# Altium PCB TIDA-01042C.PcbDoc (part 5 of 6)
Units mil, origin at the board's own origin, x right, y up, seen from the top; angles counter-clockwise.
Board outline 8300 x 7100 mil, 8 copper layers (Top Layer, Signal Layer 1, Signal Layer 2, Signal Layer 3, Signal Layer 4, Signal Layer 5, Signal Layer 6, Bottom Layer), stack 59.2 mil thick; 551 components, 303 nets, 1611 pads, 2322 vias.
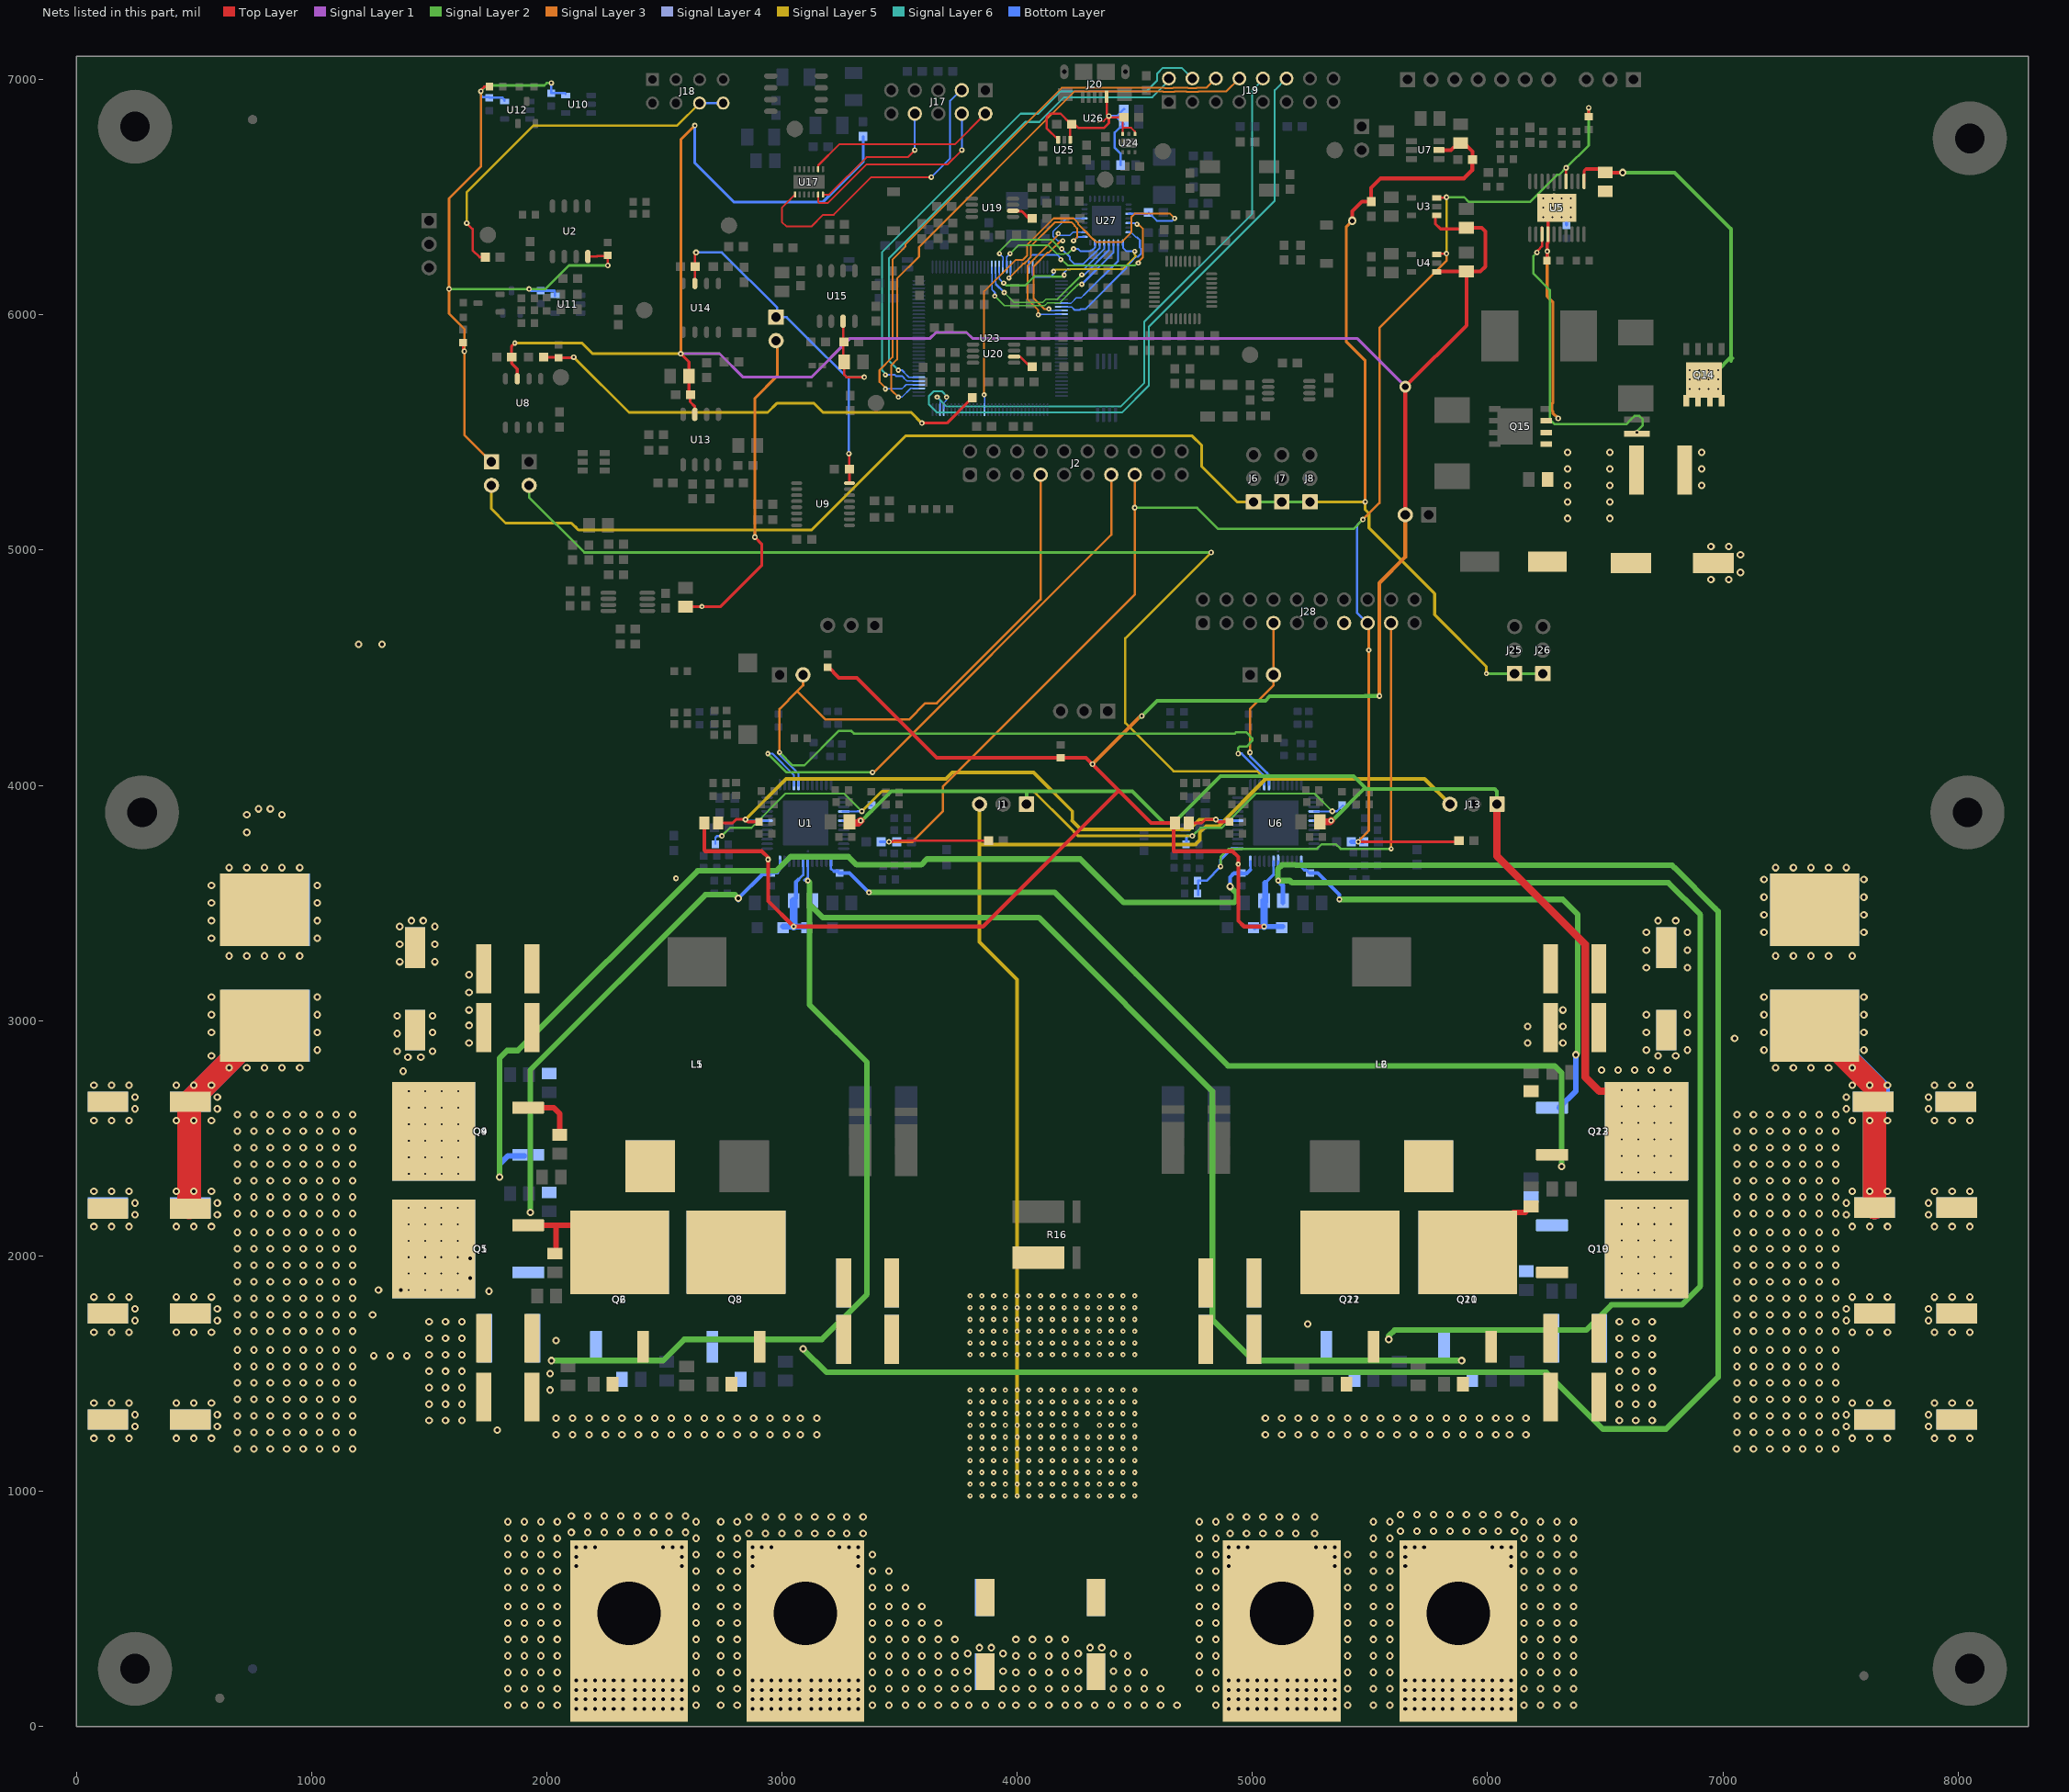
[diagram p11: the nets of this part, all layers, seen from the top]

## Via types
v1: diameter 32, hole 16, Top Layer to Bottom Layer, tented both sides, 1077 vias
v2: diameter 22, hole 8, Top Layer to Bottom Layer, tented both sides, 583 vias
v3: diameter 32, hole 16, Top Layer to Bottom Layer, 233 vias
v4: diameter 24, hole 10, Top Layer to Bottom Layer, tented both sides, 153 vias
v5: diameter 24, hole 8, Top Layer to Bottom Layer, 96 vias
v6: diameter 19.68, hole 7.87, Top Layer to Bottom Layer, 70 vias
v7: diameter 24, hole 10, Top Layer to Bottom Layer, 44 vias
v8: diameter 28, hole 8, Top Layer to Bottom Layer, tented top, 24 vias
v9: diameter 22, hole 8, Top Layer to Bottom Layer, 18 vias
v10: diameter 19.68, hole 8, Top Layer to Bottom Layer, 16 vias
v11: diameter 50, hole 28, Top Layer to Bottom Layer, 3 vias
v12: diameter 36, hole 20, Top Layer to Bottom Layer, 2 vias
v13: diameter 26, hole 12, Top Layer to Bottom Layer, 1 vias
v14: diameter 28, hole 12, Top Layer to Bottom Layer, tented both sides, 1 vias
v15: diameter 24, hole 10, Top Layer to Bottom Layer, tented top, 1 vias

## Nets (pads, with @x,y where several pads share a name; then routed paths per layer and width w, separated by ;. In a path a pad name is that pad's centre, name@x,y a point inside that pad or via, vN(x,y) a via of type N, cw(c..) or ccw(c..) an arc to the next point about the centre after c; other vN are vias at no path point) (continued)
OVPB2: C203.1 J28.17 R170.2 U6.25 | length 2057.8
  Signal Layer 2 w10: v4(4865,3655) 4865,3695 4900,3730 5275,3730 5294.87,3749.87 5355.13,3749.87 5375,3730 v2(5590,3730)
  Signal Layer 3 w10: v2(5590,3730) J28.17@5590,4690
  Bottom Layer w10: C203.1@4770,3535 4770,3595 4805,3595 v4(4865,3655)
  Bottom Layer w11: 4911.73,3731.73 U6.25@4937.6,3731.73
  Bottom Layer w12: v4(4865,3655) 4865,3685 4911.73,3731.73
PGND: C10.2 C18.2 C20.2 C21.2 C22.2 C23.2 C24.2 C25.2 C26.2 C27.2 C28.2 C29.2 C32.2 C38.2 C39.2 C40.2 C42.2 C43.2 C47.2 C48.2 C50.2 C51.2 C52.2 C53.2 C54.2 C55.2 C56.2 C57.2 C58.2 C59.2 C60.2 C61.2 C62.2 C63.2 C64.2 C65.2 C66.2 C67.2 C68.2 C69.2 C70.2 C71.2 C193.2 C206.2 C207.2 C208.2 C209.2 C210.2 C211.2 C212.2 C213.2 C214.2 C215.2 C216.2 C217.2 J11.1 J12.1 NT1.2 NT2.2 NT3.2 Q2.3 Q3.3 Q6.3 Q8.3 Q11.3 Q12.3 Q15.1 Q15.2 Q15.3 Q20.3 Q21.3 R24.2 R25.2 R35.2 R36.2 R47.1 R175.2 R176.2 R188.2 R189.2 T3.1 T4.1 U1.18 U5.13 U5.14 U5.21 U6.18 | length 23138
  Top Layer w10: v4@6215,6265 6215,6275 6231.02,6291.02 U5.13@6231.02,6342.8 U5.13@6230,6370
  Top Layer w13: C48.2@6257.44,6230 6253.63,6233.82 v4(6253.63,6270) 6253.63,6303.63 6256.61,6306.61 U5.14@6256.61,6342.8 6256.61,6416.61 U5.21@6295,6455
  Signal Layer 2 w10: v4(6210,6265) 6195,6250 6195,6175.28 6265,6105.28 6265,5555.28 6285.28,5535 6590,5535 6610.13,5555.13 6610.13,5555.3 6624.7,5569.87 6645.3,5569.87 6659.87,5555.3 6659.87,5555.13 6660,5555 6660,5540 6659.87,5539.87 6659.87,5529.87 6635,5505 v7(6635,5500)
  Signal Layer 2 w24: v1(2020,1555) 2495,1555 2585,1645 3170,1645 3361.87,1836.87 3361.87,2823.13 3116.87,3068.13 3116.87,3495 ; v1(3090,1605) 3190,1505 6249.13,1505 ; v4(3110,3595) 3116.87,3588.13 3116.87,3495 ; v1(5580,1645) 5580,1660 5605,1685 6419.92,1685 6526.8,1791.87 6825,1791.87 6904.96,1871.84 6904.96,3449.96 6768.67,3586.25 5168.59,3586.25 5159.85,3595 v4(5110,3595) 5108.13,3596.87 5108.13,3643.2 5126.8,3661.87 5183.13,3661.87 5185,3660 6785,3660 6795,3650 6795.08,3650 6968.71,3476.37 ; v1(5890,1555) 5004.92,1555 4830,1729.92 4830,2699.92 4091.8,3438.13 3173.75,3438.13 3116.87,3495 ; 6250,1505 6249.13,1505 ; 6249.13,1505 6490,1264.13 6759.13,1264.13 6980,1485 6980,3465 ; 6968.71,3476.37 6980,3465.08 6980,3465 ; 6968.71,3476.37 6968.71,3476.29 6980,3465
  Signal Layer 3 w13: v4(6253.63,6270) 6253.63,6079 6277.63,6055 6277.63,5624.92 6273.63,5620.92 6273.63,5595.08 6277.63,5591.08 6277.63,5582.37 v7(6300,5560)
  Bottom Layer w9.8: U6.18@5109.84,3677.6 5109.84,3595.16 v4(5110,3595)
  Bottom Layer w10: 3109.84,3609.63 3109.84,3609.84 U1.18@3109.84,3681.54
  Bottom Layer w12: 3095.35,3595.35 3109.84,3609.84 3110,3610
  Bottom Layer w13: C47.2@6335,6382.56 6335,6435.94 v6(6354.06,6455)
  Bottom Layer w20: v4(5110,3595) 5130,3575 C193.2@5130,3500
  other v1: 2740,90 2810,90 3385,90 3455,90 3525,90 3595,90 3665,90 3735,90 3795,90 3865,90 3935,90 3995,90 4065,90 4135,90 4205,90 4260,90 4330,90 4400,90 4470,90 4540,90 4610,90 4680,90 5515,90 5585,90 6155,90 6225,90 6295,90 6365,90 2740,160 2810,160 3385,160 3455,160 3525,160 3595,160 3665,160 3735,160 3790,160 3940,160 3995,160 4065,160 4135,160 4205,160 4260,160 4410,160 4470,160 4540,160 4610,160 5515,160 5585,160 6155,160 6225,160 6295,160 6365,160 2740,230 2810,230 3385,230 3455,230 3525,230 3595,230 3665,230 3735,230 3995,230 4065,230 4135,230 4205,230 4470,230 4540,230 5515,230 5585,230 6155,230 6225,230 6295,230 6365,230 3790,235 3940,235 4260,235 4410,235 2740,300 2810,300 3385,300 3455,300 3525,300 3595,300 3665,300 3735,300 3995,300 4065,300 4135,300 4205,300 4470,300 5515,300 5585,300 6155,300 6225,300 6295,300 6365,300 3790,310 3940,310 4260,310 4410,310 3840,335 3890,335 4310,335 4360,335 2740,370 2810,370 3385,370 3455,370 3525,370 3595,370 3665,370 3735,370 3995,370 4065,370 4135,370 4205,370 5515,370 5585,370 6155,370 6225,370 6295,370 6365,370 2740,440 2810,440 3385,440 3455,440 3525,440 3595,440 3665,440 5515,440 5585,440 6155,440 6225,440 6295,440 6365,440 2740,510 2810,510 3385,510 3455,510 3525,510 3595,510 5515,510 5585,510 6155,510 6225,510 6295,510 6365,510 2740,590 2810,590 3385,590 3455,590 3525,590 5515,590 5585,590 6155,590 6225,590 6295,590 6365,590 2740,660 2810,660 3385,660 3455,660 5515,660 5585,660 6155,660 6225,660 6295,660 6365,660 2740,730 2810,730 3385,730 5515,730 5585,730 6155,730 6225,730 6295,730 6365,730 2740,800 2810,800 5515,800 5585,800 6155,800 6225,800 6295,800 6365,800 2860,820 2930,820 3000,820 3070,820 3140,820 3210,820 3275,820 3345,820 5630,830 5700,830 5770,830 5840,830 5910,830 5980,830 6045,830 6115,830 2740,870 2810,870 5515,870 5585,870 6155,870 6225,870 6295,870 6365,870 2860,890 2930,890 3000,890 3070,890 3140,890 3210,890 3275,890 3345,890 5630,900 5700,900 5770,900 5840,900 5910,900 5980,900 6045,900 6115,900 75,1225 150,1225 225,1225 7900,1225 7975,1225 8050,1225 2040,1240 2110,1240 2180,1240 2250,1240 2320,1240 2390,1240 2460,1240 2530,1240 2600,1240 2670,1240 2740,1240 2810,1240 2880,1240 2950,1240 3020,1240 3078.24,1240 3148.24,1240 5055,1240 5125,1240 5195,1240 5265,1240 5335,1240 5405,1240 5475,1240 5545,1240 5615,1240 5685,1240 5755,1240 5825,1240 5895,1240 5965,1240 6035,1240 6093.24,1240 6163.24,1240 1790,1260 250,1275 7875,1275 2040,1310 2110,1310 2180,1310 2250,1310 2320,1310 2390,1310 2460,1310 2530,1310 2600,1310 2670,1310 2740,1310 2810,1310 2880,1310 2950,1310 3020,1310 3078.24,1310 3148.24,1310 5055,1310 5125,1310 5195,1310 5265,1310 5335,1310 5405,1310 5475,1310 5545,1310 5615,1310 5685,1310 5755,1310 5825,1310 5895,1310 5965,1310 6035,1310 6093.24,1310 6163.24,1310 250,1325 7875,1325 75,1375 150,1375 225,1375 7900,1375 7975,1375 8050,1375 2015,1430 2015,1500 2040,1640 75,1675 150,1675 225,1675 7900,1675 7975,1675 8050,1675 5235,1710 250,1725 7875,1725 250,1775 7875,1775 75,1825 150,1825 225,1825 7900,1825 7975,1825 8050,1825 75,2125 150,2125 225,2125 7900,2125 7975,2125 8050,2125 250,2175 7875,2175 250,2225 7875,2225 75,2275 150,2275 225,2275 7900,2275 7975,2275 8050,2275 75,2575 150,2575 225,2575 7900,2575 7975,2575 8050,2575 250,2625 7875,2625 250,2675 7875,2675 75,2725 150,2725 225,2725 7900,2725 7975,2725 8050,2725 6170,2905 6320,2905 6170,2975 6320,2975 6320,3045 6675,3225 6850,3225 1375,3250 1525,3250 650,3275 725,3275 800,3275 875,3275 950,3275 7225,3275 7300,3275 7375,3275 7450,3275 7550,3275 6675,3300 6850,3300 1375,3325 1525,3325 575,3350 1025,3350 6675,3375 6850,3375 7175,3375 7600,3375 1375,3400 1525,3400 575,3425 1025,3425 1425,3425 1475,3425 6725,3425 6800,3425 7175,3450 7600,3450 575,3500 1025,3500 7175,3525 7600,3525 575,3575 1025,3575 7175,3600 7600,3600 650,3650 725,3650 800,3650 875,3650 950,3650 7225,3650 7300,3650 7375,3650 7450,3650 7525,3650 725,3800 725,3875 875,3875 775,3900 825,3900 1200,4600 1300,4600 6520,5135 6340,5205 6520,5205 6340,5275 6520,5275 6340,5345 6520,5345 6340,5415 6520,5415
  other v3: 2875,75 2915,75 2955,75 2995,75 3035,75 3075,75 3125,75 3165,75 3205,75 3245,75 3285,75 3325,75 5650,75 5690,75 5730,75 5770,75 5810,75 5850,75 5900,75 5940,75 5980,75 6020,75 6060,75 6100,75 2875,115 2915,115 2955,115 2995,115 3035,115 3075,115 3125,115 3165,115 3205,115 3245,115 3285,115 3325,115 5650,115 5690,115 5730,115 5770,115 5810,115 5850,115 5900,115 5940,115 5980,115 6020,115 6060,115 6100,115 2875,155 2915,155 2955,155 2995,155 3035,155 3075,155 3125,155 3165,155 3205,155 3245,155 3285,155 3325,155 5650,155 5690,155 5730,155 5770,155 5810,155 5850,155 5900,155 5940,155 5980,155 6020,155 6060,155 6100,155 2875,195 2915,195 2955,195 2995,195 3035,195 3075,195 3125,195 3165,195 3205,195 3245,195 3285,195 3325,195 5650,195 5690,195 5730,195 5770,195 5810,195 5850,195 5900,195 5940,195 5980,195 6020,195 6060,195 6100,195 2875,681.27 3325,681.27 5650,681.27 6100,681.27 2875,721.27 3325,721.27 5650,721.27 6100,721.27 2875,761.27 2915,761.27 2955,761.27 3245,761.27 3285,761.27 3325,761.27 5650,761.27 5690,761.27 5730,761.27 6020,761.27 6060,761.27 6100,761.27 6340,5135
  other v4: 2550,3605
  other v6: 6235.94,6415.63 6275.32,6415.63 6314.69,6415.63 6354.06,6415.63 6235.94,6455 6275.32,6455 6314.69,6455 6235.94,6494.37 6275.32,6494.37 6314.69,6494.37 6354.06,6494.37
SCLK: J17.8 U17.14 | length 624.3
  Top Layer w8: U17.14@3174.06,6510.87 3200.87,6510.87 3360,6670 3535,6670 v7(3565,6700)
  Bottom Layer w8: v7(3565,6700) J17.8@3565,6855
SDIN: J17.4 U17.13 | length 889.3
  Top Layer w8: U17.13@3154.37,6510.87 3155,6510.24 3155,6480 3160,6475 3195,6475 3360,6640 3705,6640 3760,6695 v7@3760,6700
  Bottom Layer w8: v7(3765,6700) J17.4@3765,6855
SDO: J17.3 U17.8 | length 1296.1
  Top Layer w8: U17.8@3055.94,6510.87 3035,6489.92 3034.92,6489.92 3000,6455 3000,6395 3020,6375 3125,6375 3175,6425 3220,6425 3380,6585 v7(3635,6585)
  Bottom Layer w8: v7(3635,6585) 3715,6665 3715,6910 3760,6955 J17.3@3765,6955
SPI_CS: J19.6 U23.36 | length 2436.1
  Signal Layer 3 w8: v2(3440,5685) 3440,5690 3415,5715 3415,5765 3470,5820 3470,6235 3483.62,6248.62 3510.86,6275.86 3524.47,6289.47 3524.47,6299.47 4189.6,6964.6 4237.15,6964.6 4238.42,6965.87 4625.58,6965.87 4627.85,6963.6 4662.15,6963.6 4664.42,6965.87 4725.58,6965.87 4727.85,6963.6 4762.15,6963.6 4764.42,6965.87 4805.87,6965.87 J19.6@4845,7005
  Bottom Layer w6: v2(3440,5685) 3510,5685 3528.15,5703.15 U23.36@3581.85,5703.15
SPI_DONE: J19.12 U23.29 | length 2730.5
  Signal Layer 6 w8: v2(3700,5650) 3700,5655 3680,5675 3645,5675 3625,5655 3625,5620 3660,5585 4445,5585 4560,5700 4560,5950 5095,6485 5095,6955 J19.12@5145,7005
  Bottom Layer w6: U23.29@3689.09,5600 3689.09,5626.61 3700,5637.52 v2(3700,5650)
SPI_DRDY: J19.10 U23.30 | length 2500.5
  Signal Layer 6 w8: v2(3660,5650) 3700,5610 4440,5610 4540,5710 4540,5970 5000,6430 5000,6955 5045,7000 J19.10@5045,7005
  Bottom Layer w6: v2(3660,5650) 3672.4,5637.6 U23.30@3672.4,5596.85
SPI_MISO: J19.2 U23.38 | length 2123.7
  Signal Layer 4 w8: J19.2@4645,6985 J19.2@4645,7005
  Signal Layer 6 w8: v2(3495,5765) 3455,5805 3455,6240 4035,6820 4095,6820 4200,6925 4575,6925 4645,6995 J19.2@4645,7005
  Bottom Layer w6: 3520,5755 3540.35,5734.65 U23.38@3581.85,5734.65
  Bottom Layer w8: v2(3495,5765) 3510,5765 3520,5755
SPI_MOSI: J19.4 U23.37 | length 2360.2
  Signal Layer 6 w8: v2(3440,5745) 3440,5750 3425,5765 3425,6265 4015,6855 4090,6855 4185,6950 4550,6950 4595,6995 4595,7025 4620,7050 4700,7050 J19.4@4745,7005
  Bottom Layer w6: 3520,5730 3531.1,5718.9 U23.37@3581.85,5718.9
  Bottom Layer w8: v2(3440,5745) 3480,5745 3485,5740 3510,5740 3520,5730
SPI_SCLK: J19.8 U23.35 | length 2464.4
  Signal Layer 3 w8: v2(3495,5650) 3465,5680 3465,5785 3490,5810 3490,6154.25 3582.87,6247.13 3582.87,6287.87 4245,6950 4619,6950 4621.28,6947.72 4668.72,6947.72 4671,6950 4719,6950 4721.28,6947.72 4768.72,6947.72 4771,6950 4890,6950 J19.8@4945,7005
  Bottom Layer w6: v2(3495,5650) 3510,5650 3547.4,5687.4 U23.35@3581.85,5687.4
SW1: C7.1 L1.1 Q1.3 Q2.4 Q3.4 Q4.3 R22.1 R29.1 U1.24 | length 2634.9
  Top Layer w24: Q1.3@1920.33,2130 2115,2130 Q2.4@2125,2140 ; Q4.3@1935,2630 2030,2630 2055,2605 R29.1@2055,2515 ; R22.1@2040,2005 2040,2130
  Signal Layer 2 w24: v1(1930,2185) 1930,2789.92 2675.08,3535 2800,3535 v1(2815,3520)
  Bottom Layer w9.8: 2980,3630 2991.73,3641.73 U1.24@2991.73,3681.54
  Bottom Layer w16: v1@2815,3510 v1(2815,3520) 2917.56,3622.56 C7.1@2950,3622.56 ; C7.1@2950,3625 2955,3630 2980,3630
SW2: C12.2 L2.2 Q10.3 Q11.4 Q12.4 Q13.3 R33.2 R40.2 U1.13 | length 4048.4
  Top Layer w24: Q11.4@6090,2130 6090,2165 6110,2185 6160,2185 R33.2@6185,2210
  Signal Layer 2 w24: v4(3370,3545) 4160,3545 4506.33,3198.67 4506.33,3198.59 4896.8,2808.13 6285,2808.13 6315,2778.13 v1(6315,2380)
  Bottom Layer w9.8: U1.13@3208.27,3681.54 3208.27,3644.32 3222.79,3635
  Bottom Layer w16: 3222.79,3635 3237.56,3635 C12.2@3245,3627.56 3287.44,3627.56 v4(3370,3545)
SW3: C192.1 L5.2 Q5.3 Q6.4 Q8.4 Q9.3 R174.1 R182.1 U6.24 | length 4553.9
  Signal Layer 2 w24: v1(1800,2335) 1800,2840.73 1832.13,2872.87 1877.71,2872.87 2641.72,3636.87 2976.8,3636.87 2996.25,3656.33 2996.25,3656.41 3033.59,3693.75 3033.67,3693.75 3036.8,3696.87 3283.2,3696.87 3318.2,3661.87 3591.8,3661.87 3616.8,3686.87 4268.2,3686.87 4453.2,3501.87 4921.8,3501.87 4932.46,3512.54 4932.46,3542.54 v1(4905,3570)
  Bottom Layer w9.8: 4991.73,3641.73 U6.24@4991.73,3677.6
  Bottom Layer w16: v1(4905,3570) 4905,3610 4920,3625 ; C192.1@4955,3627.56 4922.56,3627.56 4920,3625 ; 4991.73,3641.73 4975,3625 4920,3625
  Bottom Layer w24: v1(1800,2335) 1800,2390 1835,2425 Q9.3@1905,2425
SW4: C195.2 L6.1 Q19.3 Q20.4 Q21.4 Q22.3 R185.2 R193.2 U6.13 | length 2155.5
  Signal Layer 2 w24: v4(5370,3515) 6319.92,3515 6383.13,3451.8 6383.13,2863.13 v1(6375,2855)
  Bottom Layer w9.8: U6.13@5208.27,3677.6 5208.27,3651.73 5220,3640
  Bottom Layer w12: 5220,3640 5230,3640 C195.2@5245,3625
  Bottom Layer w16: C195.2@5245,3627.56 5277.44,3627.56 5370,3535 v4(5370,3515) v4@5370,3510
  Bottom Layer w24: Q22.3@6305,2630 6375,2700 v1(6375,2855)
SYNC: J2.7 J3.2 U1.41 U6.40 | length 4789.2
  Signal Layer 2 w10: v2(2990,4140) 3045,4085 3095,4085 3241.13,4231.13 3294.89,4231.13 3306.01,4220 4052.23,4220 4101.58,4220 4925,4220 4930,4225 4975,4225 5000,4200 5000,4190 4975,4165 4945,4165 4940,4160 v4(4940,4135)
  Signal Layer 3 w10: v2(2990,4140) 2990,4325 3065,4400 ; J3.2@3090,4470 3090,4425 3065,4400 ; J2.7@4100,5320 4100,4790.28 3658.6,4348.87 3610.11,4348.87 3541.24,4280 3185,4280 3065,4400
  Bottom Layer w8: v2@2985,4145 v2(2990,4140) 2990,4130 3070.38,4049.62 3070.38,4047.28 3070.47,4047.19 U1.41@3070.47,3998.46
  Bottom Layer w9.8: v4@4935,4135 v4(4940,4135) 4955,4135 5044.33,4045.67 5044.33,4045.37 5050.79,4038.91 U6.40@5050.79,4002.4
SYNCIN: J2.13 U1.40 | length 2360.6
  Signal Layer 2 w10: v2(2940,4135) 3020,4055 v4(3385,4055)
  Signal Layer 3 w10: v4@3385,4050 v4(3385,4055) ; v4@3390,4055 4400,5065 J2.13@4400,5320
  Bottom Layer w8: v2(2940,4135) 2960,4135 3050.79,4044.21 U1.40@3050.79,3998.46
SYNCIN2: J28.13
SYNCn: J17.2 U17.2 | length 820.1
  Top Layer w8: U17.2@3154.37,6619.13 3154.37,6635.61 3243.76,6725 3735,6725 J17.2@3865,6855
  Bottom Layer w8: J17.2@3865,6855 J17.2@3866.5,6853.5
SYNCOUT2: J27.2 J28.7 U6.41 | length 757.4
  Signal Layer 3 w10: v4@4990,4150 4990,4325 5090,4425 J27.2@5090,4470 J28.7@5090,4690
  Bottom Layer w9.8: v4@4990,4145 v4(4990,4140) 4990,4125 5062,4053 5062,4052.69 5070.47,4044.22 U6.41@5070.47,4002.4
USB_VBUS: C179.1 C182.1 C187.2 C188.1 J20.1 R149.2 U24.4 U24.6 U25.1 U25.3 U26.6 | length 1197.9
  Top Layer w8: U26.6@4344.69,6823.19 4368.19,6823.19 4387.5,6842.5 v7(4390,6845) ; U24.6@4449.41,6768.39 C179.1@4449.41,6834.41 ; 4450,6795 4485,6795 4500.59,6779.41 U24.4@4500.59,6768.39
  Top Layer w10: U25.3@4174.41,6744.29 4125,6793.7 4125,6840 4140,6855 4185,6855 C182.1@4225,6815 ; U25.1@4225.59,6744.29 4225.59,6800.59 C182.1@4235,6810 ; C182.1@4231.5,6810 C182.1@4235,6810 ; J20.1@4381.18,6937.6 J20.1@4381.18,6927.6 4381.18,6853.82 v7(4390,6845) 4395,6840 C179.1@4453.5,6840 ; v7@4387.5,6842.5 4390,6840 4390,6815 4370,6795 4260,6795 4245,6810 C182.1@4235,6810 ; C179.1@4449.41,6834.41 C179.1@4450,6835 ; C179.1@4450,6830 C179.1@4450,6835 ; C179.1@4455,6840 C179.1@4450,6835
  Bottom Layer w10: v7(4390,6845) 4420,6845 ; R149.2@4440,6636.5 4440,6685 4415,6710 4415,6775 C187.2@4450,6810 ; C187.2@4453.5,6810 4420,6843.5 4420,6845 ; C188.1@4455,6875 4425,6845 4420,6845
USBCLK: U23.92 U27.1 | length 640.8
  Signal Layer 5 w8: v2(4155,6185) 4161.87,6191.87 4189.53,6191.87 ; 4189.53,6191.88 4210.47,6191.88 4221.88,6191.88 4225,6195 ; 4210.47,6191.87 4224.53,6191.87 4227.65,6195 4450,6195 4505,6250 4500,6255 v2(4500,6270)
  Bottom Layer w6: U23.92@4066.1,6203.15 4066.1,6168.9 4075,6160
  Bottom Layer w8: 4075.41,6160.41 4075.75,6160.75 4140.75,6160.75 4160.51,6180.51 v2@4160.51,6190 ; U27.1@4450,6305 4450,6285 4465,6270 v2(4500,6270)
USBD0: U23.81 U27.3 | length 790.3
  Signal Layer 2 w6: v2(3905,6080) 3945.75,6039.25 4114.81,6039.25 4115.56,6040 4118.13,6040 4128.13,6050 4180,6050 4245,6115
  Signal Layer 2 w8: v2@3905,6075 v2(3905,6080) ; 4245,6115 4260,6130 v2(4275,6130)
  Bottom Layer w6: U23.81@3892.87,6203.15 3892.87,6107.13 3900,6100
  Bottom Layer w8: 3900,6100 3905,6095 v2(3905,6080) ; v2(4275,6130) 4410,6265 U27.3@4410,6305 ; U27.3@4409.53,6305 U27.3@4409.53,6306.69
USBD1: U23.82 U27.4 | length 716.2
  Signal Layer 2 w6: v2(3945,6095) 3986.87,6053.13 4109.06,6053.13 4121.68,6065.75 4170.75,6065.75
  Signal Layer 2 w8: 4170.75,6065.75 v2(4275,6170)
  Bottom Layer w6: U23.82@3908.62,6203.15 3908.62,6131.38 3910,6130
  Bottom Layer w8: 3910,6130 v2(3945,6095) ; v2@4270,6165 v2(4275,6170) 4285,6170 4390,6275 U27.4@4390,6295 ; U27.4@4389.84,6295 U27.4@4389.84,6306.69
USBD2: U23.83 U27.5 | length 593.3
  Signal Layer 2 w8: v2(3942.88,6134.87) 3952.75,6125 4035,6125 4075,6165 4142.65,6165 4145.53,6162.13 4192.13,6162.13 v2@4200,6170
  Bottom Layer w6: U23.83@3924.37,6203.15 3924.37,6155.63 3925,6155
  Bottom Layer w8: 3925,6152.75 v2(3942.88,6134.87) ; v2(4200,6169) 4200,6180 4215,6195 4285,6195 4370,6280 U27.5@4370,6295
USBD3: U23.84 U27.6 | length 632.6
  Signal Layer 2 w8: v2(3925,6260) 3925,6270 3975,6320 4145,6320 4185,6280 v2(4190,6280) v2@4195,6275
  Bottom Layer w6: v2(3925,6260) 3940.12,6244.88 U23.84@3940.12,6203.15
  Bottom Layer w8: v2(3925,6260) v2@3930,6260 ; v2(4190,6280) 4225,6245 4225,6235 4245,6215 4280,6215 4319.13,6254.13 4321.58,6254.13 4350.47,6283.02 U27.6@4350.47,6306.69
USBD4: U23.85 U27.7 | length 497.8
  Signal Layer 2 w6: 4168.13,6260 4179.07,6260 4180.94,6258.13 4199.06,6258.13 4200.93,6260 4215,6260
  Signal Layer 2 w8: v2(3970,6260) 4005,6295 4133.13,6295 4168.13,6260 ; 4215,6260 4235,6280 v2(4240,6280)
  Bottom Layer w6: U23.85@3955.87,6203.15 3955.87,6245.87 v2(3970,6260)
  Bottom Layer w8: v2@3965,6260 v2(3970,6260) ; v2(4240,6280) 4260,6280 4270,6270 4310,6270 4315,6275 4320,6275 4330,6285 ; 4330.79,6285.79 U27.7@4330.79,6306.69
USBD5: U23.86 U27.9 | length 585.3
  Signal Layer 3 w8: v2(3965.35,6156.75) 4025.85,6217.25 4029.7,6217.25 4034.7,6222.25 4035.64,6222.25 4057.75,6244.36 4057.75,6290.3 4161.58,6394.13 4230.87,6394.13 4244.13,6380.87 4244.13,6378.42 4255,6367.55 4255,6330 v2(4240,6315)
  Bottom Layer w6: v2@3965,6160 3971.61,6166.61 U23.86@3971.61,6203.15
  Bottom Layer w8: v2(4240,6315) 4256.1,6331.1 U27.9@4286.69,6331.1
USBD6: U23.106 U27.10 | length 636.4
  Signal Layer 3 w8: v2(4090,6000) 4090,6020 4045,6065 4045,6209.17 4073.62,6237.79 4073.62,6238.62 4175,6340 v2(4175,6345)
  Bottom Layer w6: v2(4090,6000) 4092.36,6002.36 U23.106@4188.15,6002.36 ; v2(4175,6345) 4181.87,6338.13 4224.16,6338.13 4236.82,6350.79 U27.10@4286.69,6350.79
USBD7: U23.105 U27.13 | length 670.9
  Signal Layer 3 w8: v2(4135,6025) 4115,6025 4070,6070 4070,6205 4130,6265 4135,6265 4185,6315 v2(4194.25,6315)
  Bottom Layer w6: v2(4135,6025) 4141.89,6018.11 U23.105@4188.15,6018.11 ; v2@4195,6315 v2(4194.25,6315) 4172.19,6315 4153.13,6334.07 4153.13,6354.06 4189.07,6390 4190,6390 4209.84,6409.84 U27.13@4286.69,6409.84
USBDIR: U23.104 U27.31 | length 569.8
  Bottom Layer w6: U23.104@4188.15,6033.86 4231.14,6033.86 4240,6025 ; U27.31@4473.31,6350.79 4484.54,6350.79 4505.33,6330 4510,6330
  Bottom Layer w8: 4240,6025 4245,6020 4266.24,6020 4270.11,6023.87 4288.87,6023.87 4465,6200 4465,6205 4492.13,6232.13 4492.13,6234.47 4504.78,6247.13 4514.47,6247.13 4527.84,6260.49 4526.94,6261.38 4526.94,6280.4 4521.87,6285.47 4521.87,6318.13 4511.21,6328.79
USBNXT: U23.103 U27.2 | length 392.9
  Bottom Layer w6: U23.103@4188.15,6049.61 4229.61,6049.61 4252.87,6072.87 4272.87,6072.87 4290,6090
  Bottom Layer w8: 4290,6090 4429.21,6229.21 U27.2@4429.21,6306.69
USBRST: R154.2 U23.18 U27.27 | length 1827.9
  Signal Layer 3 w8: v2(3860,5660) 3860,6100 3993.13,6233.13 4023.13,6233.13 4028.13,6238.13 4029.06,6238.13 4041.87,6250.94 4041.87,6296.87 4155,6410 4240,6410 4260,6390 4260,6385 4306.13,6338.87 4306.13,6338.27 4308.28,6336.12 4308.28,6336 4321,6323.28 4321.72,6323.28 4335,6310 4445,6310 4485,6350 4485,6415 4500,6430 4650,6430 v2(4670,6410)
  Bottom Layer w6: v2(3860,5660) 3861.38,5658.62 U23.18@3861.38,5596.85
  Bottom Layer w8: U27.27@4473.31,6429.53 4554.53,6429.53 R154.2@4559.25,6434.25 ; R154.2@4558.5,6435 R154.2@4559.25,6434.25 ; v2(4670,6410) 4660,6400 4593.5,6400 R154.2@4559.25,6434.25
USBSTP: U23.91 U27.29 | length 756.8
  Signal Layer 2 w8: v2(4185.73,6234.63) 4189.63,6234.63 4190,6235 4215,6210 4500,6210 4510,6220 v2(4515,6220)
  Signal Layer 3 w8: v2(4510,6385) 4515,6385 4535,6365 4535,6245 4515,6225 v2(4515,6220)
  Bottom Layer w6: U23.91@4050.35,6203.15 4050.35,6240.35 4065,6255
  Bottom Layer w8: 4065,6255 4170,6255 4185.73,6239.27 v2(4185.73,6234.63) ; U27.29@4473.31,6390.16 v2@4509.84,6390.16
UVLO: J2.15 J28.15 R4.1 R6.2 R34.1 R45.2 R53.1 R60.2 R87.2 U3.3 U4.3 U5.4 | length 8007.4
  Top Layer w10: v4@3450,3760 v4(3455,3760) 3470,3760 3475,3765 R4.1@3878.5,3765 R4.1@3882.44,3765 ; v4(5450,3760) 5875,3760 R34.1@5880,3765 ; U3.3@5777.24,6497.4 U3.3@5784.13,6497.4 5822.4,6497.4 v4(5825,6500) ; U4.3@5785,6260 v4(5825,6260) ; U5.4@6333.39,6567.2 v4@6333.39,6618.39 ; R53.1@6430,6845 v4(6430,6880)
  Signal Layer 2 w10: v4(4500,5180) 4765,5180 4855,5090 5430,5090 v7(5470,5130) ; v4(5825,6500) 5900,6500 5920,6480 6000,6480 6180.07,6480.07 6295,6595 6304.1,6595 v4(6334.1,6625) 6335,6625 6430,6720 v4(6430,6880)
  Signal Layer 3 w10: v4@3455,3755 3460,3760 3555,3760 3685,3890 3685,3995.56 4500,4810.56 v4(4500,5180) 4500,5295 J2.15@4505,5300 ; v4@5447.5,3760 5495,3807.5 v2(5495,4575) 5495,4660 J28.15@5490,4665 ; v7(5470,5130) 5540,5200 5540,5945 5825,6230 v4(5825,6260)
  Signal Layer 5 w10: v4(5825,6260) v4(5825,6500)
  Bottom Layer w10: R60.2@3417.56,3760 R60.2@3421.5,3760 v4(3455,3760) R6.2@3488.5,3760 R6.2@3490,3760 ; v7(5470,5130) 5445,5105 5445,4735 J28.15@5490,4690
  Bottom Layer w20: R45.2@5421.5,3760 v4(5450,3760) R87.2@5470,3760
V5: C99.2 C111.1 C116.1 C117.1 J14.1 U9.16 U14.7 U15.7 | length 1873.3
  Top Layer w10: U14.7@2630,6133.35 2630,6260 v13(2635,6265) ; C116.1@3255,5890 3260,5885 C117.1@3260,5800 ; U15.7@3260,5970 3260,5888.5 C116.1@3263.5,5885 ; C117.1@3265,5800 3265,5745 3275,5735 v4(3350,5735) ; C99.2@3285,5355 3287.2,5352.8 U9.16@3287.2,5284.57 ; C99.2@3286.5,5355 v4@3286.5,5408.5
  Bottom Layer w10: v13(2635,6265) 2745,6265 2980,6030 J14.1@2980,5990 ; J14.1@2975,5985 J14.1@2980,5990 ; 3280,5735 3285,5730 v4(3285,5410) ; v4(3350,5735) 3275,5735 3110,5900 3020,5990 J14.1@2980,5990
V5.0_Control: C76.1 J6.1 J7.1 J8.1 J14.2 J25.1 J26.1 J37.2 L7.2 R10.1 R164.2 U7.5 | length 8939
  Top Layer w12: L7.2@2590,4760 v2(2660,4760) 2740,4760 2913.65,4933.65 2913.65,5026.35 v7(2885,5055)
  Top Layer w16: v12(5425,6400) 5425,6440 5466.5,6481.5 R164.2@5505,6481.5 5505,6540 5545,6580 5900,6580 5935,6615 R10.1@5935,6655 ; U7.5@5790,6700 U7.5@5793.07,6700 5845,6700 5875,6730 C76.1@5885,6730 ; C76.1@5905,6725 5936.5,6693.5 R10.1@5936.5,6660
  Signal Layer 2 w12: J6.1@5005,5205 J7.1@5125,5205 J8.1@5245,5205 ; v2(5995,4475) J25.1@6115,4475 J26.1@6235,4475
  Signal Layer 3 w12: v7(2885,5055) 2885,5645 2980,5740 J14.2@2980,5895 ; v12(5425,6400) 5400,6375 5400,5885 5480,5805 v4(5480,5205)
  Signal Layer 5 w10: J6.1@5005,5205 J6.1@5015,5205
  Signal Layer 5 w12: J37.2@1765,5275 1765,5175 1825,5115 2105,5115 2120.13,5099.87 2120.3,5099.87 2134.87,5085.3 2134.87,5085 2885,5085 ; v7(2885,5055) 2885,5085 ; J6.1@5005,5205 4935,5205 4785,5355 4785,5445 4745,5485 3525,5485 3125,5085 2885,5085 ; J8.1@5245,5205 v4(5480,5205) 5480,5171.75 5495.87,5155.87 5495.87,5094.13 5775,4815 5775,4725 5995,4505 v2(5995,4475)
V5A: C84.1 C91.2 C93.1 C94.2 J37.1 R90.1 R91.1 U2.8 U10.5 U11.5 U12.5 | length 3298
  Top Layer w10: R90.1@1645,5880 1645,5850 v4(1650,5845) ; v4@1720,6955 1735,6970 R91.1@1757.44,6970 ; U2.8@2175,6247.72 2212.72,6247.72 2215,6250 2260,6250 v4(2260,6210)
  Signal Layer 2 w10: v4(1585,6110) v4(1925,6110) 1995,6110 2095,6210 v4(2260,6210) ; v4(1720,6950) 1745,6975 1990,6975 2000,6985 v4(2020,6985)
  Signal Layer 3 w10: v4(1720,6950) 1720,6630 1585,6495 v4(1585,6110) 1585,6005 1650,5940 v4(1650,5845) 1650,5490 J37.1@1765,5375
  Bottom Layer w10: v4(1720,6950) 1720,6935 1730,6925 C91.2@1755,6925 ; C91.2@1755,6922.56 1812.44,6922.56 1820,6915 U12.5@1820,6910 ; v4(1925,6110) 1932.44,6102.56 C93.1@1975,6102.56 2032.44,6102.56 2035,6100 U11.5@2035,6080 ; v4@2020,6975 C94.2@2020,6942.56 2077.44,6942.56 U10.5@2080,6940
V_HV: C6.1 C18.1 C22.1 C23.1 C24.1 C25.1 C32.1 C33.1 C38.1 C39.1 C40.1 C50.1 C51.1 C52.1 C53.1 C56.1 C57.1 C58.1 C59.1 C60.1 C61.1 C62.1 C63.1 C64.1 C65.1 C66.1 C67.1 C206.1 C207.1 C208.1 C209.1 C210.1 C211.1 C212.1 C213.1 C214.1 C215.1 C216.1 C217.1 J1.1 J9.1 J13.1 Q1.4 Q4.4 Q5.4 Q9.4 Q10.4 Q13.4 Q14.5 Q14.6 Q14.7 Q14.8 Q14.9 Q19.4 Q22.4 T1.1 U1.6 U5.1 U6.6 | length 10068.2
  Top Layer w10: C40.1@6485,6620 C40.1@6500,6605
  Top Layer w13: U5.1@6410.16,6567.2 6410.16,6610.16 6420,6620
  Top Layer w16: 6420,6620 C40.1@6485,6620 ; C40.1@6500,6605 v1(6575,6605)
  Top Layer w30: C33.1@5290,3845 5330,3845 v4(5334.84,3849.84)
  Top Layer w32: C6.1@3285.43,3840 3325,3840 v4(3334.84,3849.84) ; J13.1@6040,3925 J13.1@6040,3920 6040,3700 6415,3325 6415,2760 6475,2700 Q13.4@6570,2700
  Top Layer w100: C56.1@480.2,2205 480.2,2655.2 803.94,2978.94 C18.1@813.94,2978.94 ; C32.1@7390,2978.94 7386.06,2978.94 7542.5,2822.5 7645,2720 C53.1@7645,2655 ; C59.1@7644.8,2205 7644.8,2654.8 C53.1@7645,2655 ; 7645,2610 C53.1@7645,2655
  Signal Layer 2 w16: v4(3334.84,3849.84) 3339.84,3849.84 3380,3890 ; 3382.5,3892.5 3465,3975 4040,3975 ; J1.1@4040,3920 4040,3975 ; v4@5339.84,3849.84 5474.18,3984.18 6030.75,3984.18 6040,3975.09 J13.1@6040,3920 ; 5485,3985 5430,4040 4865,4040 4665,3840 4625,3840 4490,3975 4040,3975 ; v1(6575,6605) 6795,6605 7035,6365 7035,5815 ; v8(6980,5765) 7030,5815 7035,5815 ; 7035,5805 7035,5815 ; 7040,5815 7035,5815
  Bottom Layer w9.8: U1.6@3258.46,3849.84 v4(3334.84,3849.84) ; U6.6@5262.4,3849.84 5330.16,3849.84 v4@5335,3845
  Bottom Layer w10: C208.1@465,2220 C208.1@480.2,2235.2
  Bottom Layer w100: C208.1@480.2,2235.2 480.2,2655 810,2984.8 C211.1@810,2985 ; C217.1@7390,2978.94 7660,2708.94 C213.1@7660,2640 ; C213.1@7640,2665 7644.8,2660.2 C214.1@7644.8,2205
  other v1: 1835,90 1905,90 1975,90 2045,90 2635,90 1835,160 1905,160 1975,160 2045,160 2635,160 1835,230 1905,230 1975,230 2045,230 2635,230 1835,300 1905,300 1975,300 2045,300 2635,300 1835,370 1905,370 1975,370 2045,370 2635,370 1835,440 1905,440 1975,440 2045,440 2635,440 1835,510 1905,510 1975,510 2045,510 2635,510 1835,590 1905,590 1975,590 2045,590 2635,590 1835,660 1905,660 1975,660 2045,660 2635,660 1835,730 1905,730 1975,730 2045,730 2635,730 1835,800 1905,800 1975,800 2045,800 2635,800 2105,825 2175,825 2245,825 2315,825 2385,825 2455,825 2520,825 2590,825 1835,870 1905,870 1975,870 2045,870 2635,870 2105,895 2175,895 2245,895 2315,895 2385,895 2455,895 2520,895 2590,895 685,1180 755,1180 825,1180 895,1180 965,1180 1035,1180 1105,1180 1175,1180 7060,1180 7130,1180 7200,1180 7270,1180 7340,1180 7410,1180 7480,1180 425,1225 500,1225 575,1225 7550,1225 7625,1225 7700,1225 685,1250 755,1250 825,1250 895,1250 965,1250 1035,1250 1105,1250 1175,1250 7060,1250 7130,1250 7200,1250 7270,1250 7340,1250 7410,1250 7480,1250 600,1275 7525,1275 1500,1300 1570,1300 1640,1300 6560,1300 6630,1300 6700,1300 685,1320 755,1320 825,1320 895,1320 965,1320 1035,1320 1105,1320 1175,1320 7060,1320 7130,1320 7200,1320 7270,1320 7340,1320 7410,1320 7480,1320 600,1325 7525,1325 1500,1370 1570,1370 1640,1370 6560,1370 6630,1370 6700,1370 425,1375 500,1375 575,1375 7550,1375 7625,1375 7700,1375 685,1390 755,1390 825,1390 895,1390 965,1390 1035,1390 1105,1390 1175,1390 7060,1390 7130,1390 7200,1390 7270,1390 7340,1390 7410,1390 7480,1390 1500,1440 1570,1440 1640,1440 6560,1440 6630,1440 6700,1440 685,1460 755,1460 825,1460 895,1460 965,1460 1035,1460 1105,1460 1175,1460 7060,1460 7130,1460 7200,1460 7270,1460 7340,1460 7410,1460 7480,1460 1500,1510 1570,1510 1640,1510 6560,1510 6630,1510 6700,1510 685,1530 755,1530 825,1530 895,1530 965,1530 1035,1530 1105,1530 1175,1530 7060,1530 7130,1530 7200,1530 7270,1530 7340,1530 7410,1530 7480,1530 1265,1575 1335,1575 1405,1575 1500,1580 1570,1580 1640,1580 6560,1580 6630,1580 6700,1580 685,1600 755,1600 825,1600 895,1600 965,1600 1035,1600 1105,1600 1175,1600 7060,1600 7130,1600 7200,1600 7270,1600 7340,1600 7410,1600 7480,1600 1500,1650 1570,1650 1640,1650 6560,1650 6630,1650 6700,1650 425,1675 500,1675 575,1675 7550,1675 7625,1675 7700,1675 685,1680 755,1680 825,1680 895,1680 965,1680 1035,1680 1105,1680 1175,1680 7060,1680 7130,1680 7200,1680 7270,1680 7340,1680 7410,1680 7480,1680 1500,1720 1570,1720 1640,1720 6560,1720 6630,1720 6700,1720 600,1725 7525,1725 685,1750 755,1750 825,1750 895,1750 965,1750 1035,1750 1105,1750 1175,1750 1260,1750 7060,1750 7130,1750 7200,1750 7270,1750 7340,1750 7410,1750 7480,1750 600,1775 7525,1775 685,1820 755,1820 825,1820 895,1820 965,1820 1035,1820 1105,1820 1175,1820 7060,1820 7130,1820 7200,1820 7270,1820 7340,1820 7410,1820 7480,1820 425,1825 500,1825 575,1825 7550,1825 7625,1825 7700,1825 1755,1850 1285,1855 1380,1855 685,1890 755,1890 825,1890 895,1890 965,1890 1035,1890 1105,1890 1175,1890 7060,1890 7130,1890 7200,1890 7270,1890 7340,1890 7410,1890 7480,1890 1675,1905 685,1960 755,1960 825,1960 895,1960 965,1960 1035,1960 1105,1960 1175,1960 7060,1960 7130,1960 7200,1960 7270,1960 7340,1960 7410,1960 7480,1960 1675,1990 685,2030 755,2030 825,2030 895,2030 965,2030 1035,2030 1105,2030 1175,2030 7060,2030 7130,2030 7200,2030 7270,2030 7340,2030 7410,2030 7480,2030 685,2100 755,2100 825,2100 895,2100 965,2100 1035,2100 1105,2100 1175,2100 7060,2100 7130,2100 7200,2100 7270,2100 7340,2100 7410,2100 7480,2100 425,2125 500,2125 575,2125 7550,2125 7625,2125 7700,2125 600,2175 7525,2175 685,2180 755,2180 825,2180 895,2180 965,2180 1035,2180 1105,2180 1175,2180 7060,2180 7130,2180 7200,2180 7270,2180 7340,2180 7410,2180 7480,2180 600,2225 7525,2225 685,2250 755,2250 825,2250 895,2250 965,2250 1035,2250 1105,2250 1175,2250 7060,2250 7130,2250 7200,2250 7270,2250 7340,2250 7410,2250 7480,2250 425,2275 500,2275 575,2275 7550,2275 7625,2275 7700,2275 685,2320 755,2320 825,2320 895,2320 965,2320 1035,2320 1105,2320 1175,2320 7060,2320 7130,2320 7200,2320 7270,2320 7340,2320 7410,2320 7480,2320 685,2390 755,2390 825,2390 895,2390 965,2390 1035,2390 1105,2390 1175,2390 7060,2390 7130,2390 7200,2390 7270,2390 7340,2390 7410,2390 7480,2390 685,2460 755,2460 825,2460 895,2460 965,2460 1035,2460 1105,2460 1175,2460 7060,2460 7130,2460 7200,2460 7270,2460 7340,2460 7410,2460 7480,2460 685,2530 755,2530 825,2530 895,2530 965,2530 1035,2530 1105,2530 1175,2530 7060,2530 7130,2530 7200,2530 7270,2530 7340,2530 7410,2530 7480,2530 425,2575 500,2575 575,2575 7550,2575 7625,2575 7700,2575 685,2600 755,2600 825,2600 895,2600 965,2600 1035,2600 1105,2600 1175,2600 7060,2600 7130,2600 7200,2600 7270,2600 7340,2600 7410,2600 7480,2600 600,2625 7525,2625 600,2675 7525,2675 425,2725 500,2725 575,2725 7550,2725 7625,2725 7700,2725 1390,2785 6485,2790 6555,2790 6625,2790 6695,2790 6765,2790 650,2800 725,2800 800,2800 875,2800 950,2800 7225,2800 7300,2800 7375,2800 7450,2800 7550,2800 1410,2845 1465,2845 575,2850 6725,2850 6800,2850 1365,2870 1515,2870 1025,2875 6675,2875 6850,2875 7175,2875 7600,2875 1670,2905 7050,2925 1365,2945 575,2950 1025,2950 1515,2950 6675,2950 6850,2950 7175,2950 7600,2950 1670,2980 1365,3020 1515,3020 575,3025 1025,3025 6675,3025 6850,3025 7175,3025 7600,3025 1670,3045 575,3100 1025,3100 7175,3100 7600,3100 1670,3120 1670,3195 6950,4875 7025,4875 7075,4905 7075,4980 6950,5015 7025,5015 6910,5275 6910,5345 6910,5415
  other v3: 2125,75 2165,75 2205,75 2245,75 2285,75 2325,75 2375,75 2415,75 2455,75 2495,75 2535,75 2575,75 2125,115 2165,115 2205,115 2245,115 2285,115 2325,115 2375,115 2415,115 2455,115 2495,115 2535,115 2575,115 2125,155 2165,155 2205,155 2245,155 2285,155 2325,155 2375,155 2415,155 2455,155 2495,155 2535,155 2575,155 2125,195 2165,195 2205,195 2245,195 2285,195 2325,195 2375,195 2415,195 2455,195 2495,195 2535,195 2575,195 2125,681.27 2575,681.27 2125,721.27 2575,721.27 2125,761.27 2165,761.27 2205,761.27 2495,761.27 2535,761.27 2575,761.27
  other v5: 1412.7,1854.45 1482.7,1854.45 1552.7,1854.45 1622.7,1854.45 6570,1855 6640,1855 6710,1855 6780,1855 1412.7,1924.45 1482.7,1924.45 1552.7,1924.45 1622.7,1924.45 6570,1925 6640,1925 6710,1925 6780,1925 1412.7,1994.45 1482.7,1994.45 1552.7,1994.45 1622.7,1994.45 6570,1995 6640,1995 6710,1995 6780,1995 1412.7,2064.45 1482.7,2064.45 1552.7,2064.45 1622.7,2064.45 6570,2065 6640,2065 6710,2065 6780,2065 1412.7,2134.45 1482.7,2134.45 1552.7,2134.45 1622.7,2134.45 6570,2135 6640,2135 6710,2135 6780,2135 1412.7,2204.45 1482.7,2204.45 1552.7,2204.45 1622.7,2204.45 6570,2205 6640,2205 6710,2205 6780,2205 1414.19,2349.37 1484.19,2349.37 1554.19,2349.37 1624.19,2349.37 6570,2355 6640,2355 6710,2355 6780,2355 1414.19,2419.37 1484.19,2419.37 1554.19,2419.37 1624.19,2419.37 6570,2425 6640,2425 6710,2425 6780,2425 1414.19,2489.37 1484.19,2489.37 1554.19,2489.37 1624.19,2489.37 6570,2495 6640,2495 6710,2495 6780,2495 1414.19,2559.37 1484.19,2559.37 1554.19,2559.37 1624.19,2559.37 6570,2565 6640,2565 6710,2565 6780,2565 1414.19,2629.37 1484.19,2629.37 1554.19,2629.37 1624.19,2629.37 6570,2635 6640,2635 6710,2635 6780,2635 1414.19,2699.37 1484.19,2699.37 1554.19,2699.37 1624.19,2699.37 6570,2705 6640,2705 6710,2705 6780,2705
  other v8: 6860,5685 6900,5685 6940,5685 6980,5685 6860,5725 6900,5725 6940,5725 6980,5725 6860,5765 6900,5765 6940,5765
V_LV: C20.1 C21.1 C26.1 C27.1 C28.1 C29.1 C54.1 C55.1 C68.1 C69.1 C70.1 C71.1 J1.3 J10.1 J13.3 J35.2 R16.4 T2.1 | length 9831.7
  Signal Layer 2 w10: J35.2@1925,5275 1925,5225 2160,4990 v7(4825,4990)
  Signal Layer 2 w16: J1.3@3840,3920 J1.3@3840,3946.13
  Signal Layer 5 w10: v7(4825,4990) 4460,4625 4460,4265 4665,4060 5020,4060 5054.71,4025.29 5055,4025
  Signal Layer 5 w16: J1.3@3840,3920 3840,3745 ; v2(4000,980) v2(4000,1230) v2(4000,1430) 4000,1570 4000,1620 4000,1920 4000,3175 3840,3335 3840,3745 ; J13.3@5840,3920 5732.13,4027.87 5057.29,4027.87 5054.71,4025.29 4856.55,3827.13 4803.83,3827.13 4777.13,3800.42 4777.13,3767.13 4757.87,3747.87 3842.87,3747.87 3840,3745
  other v1: 4845,90 5405,90 4775,160 4845,160 5405,160 4775,230 4845,230 5405,230 4775,300 4845,300 5405,300 4775,370 4845,370 5405,370 4775,440 4845,440 5405,440 4775,510 4845,510 5405,510 4775,590 4845,590 5405,590 4775,660 4845,660 5405,660 4775,730 4845,730 5405,730 4775,800 4845,800 4905,820 4975,820 5045,820 5115,820 5185,820 5265,820 4775,870 4845,870 4905,890 4975,890 5045,890 5115,890 5185,890 5265,890
  other v2: 3800,980 3850,980 3900,980 3950,980 4050,980 4100,980 4150,980 4200,980 4250,980 4300,980 4350,980 4400,980 4450,980 4500,980 3800,1030 3850,1030 3900,1030 3950,1030 4000,1030 4050,1030 4150,1030 4200,1030 4250,1030 4300,1030 4400,1030 4450,1030 4500,1030 3800,1080 3850,1080 3900,1080 3950,1080 4000,1080 4050,1080 4100,1080 4150,1080 4200,1080 4250,1080 4300,1080 4350,1080 4400,1080 4450,1080 4500,1080 3800,1130 3850,1130 3900,1130 3950,1130 4000,1130 4050,1130 4100,1130 4150,1130 4200,1130 4250,1130 4300,1130 4350,1130 4400,1130 4450,1130 4500,1130 3800,1180 3850,1180 3900,1180 3950,1180 4000,1180 4050,1180 4100,1180 4150,1180 4200,1180 4250,1180 4300,1180 4350,1180 4400,1180 4450,1180 4500,1180 3800,1230 3850,1230 3900,1230 3950,1230 4050,1230 4100,1230 4150,1230 4200,1230 4250,1230 4300,1230 4350,1230 4400,1230 4450,1230 4500,1230 3800,1280 3850,1280 3900,1280 3950,1280 4000,1280 4050,1280 4100,1280 4150,1280 4200,1280 4250,1280 4350,1280 4400,1280 4450,1280 4500,1280 3800,1330 3850,1330 3900,1330 3950,1330 4000,1330 4050,1330 4150,1330 4200,1330 4250,1330 4300,1330 4400,1330 4450,1330 4500,1330 3800,1380 3850,1380 3900,1380 3950,1380 4000,1380 4050,1380 4100,1380 4150,1380 4200,1380 4250,1380 4300,1380 4350,1380 4400,1380 4450,1380 4500,1380 3800,1430 3850,1430 3900,1430 3950,1430 4050,1430 4100,1430 4150,1430 4200,1430 4250,1430 4300,1430 4350,1430 4400,1430 4450,1430 4500,1430 3800,1580 3850,1580 3900,1580 3950,1580 4000,1580 4050,1580 4100,1580 4150,1580 4200,1580 4250,1580 4300,1580 4350,1580 4400,1580 4450,1580 4500,1580 3800,1630 3850,1630 3900,1630 3950,1630 4000,1630 4050,1630 4100,1630 4150,1630 4200,1630 4250,1630 4300,1630 4350,1630 4400,1630 4450,1630 4500,1630 3800,1680 3850,1680 3900,1680 3950,1680 4000,1680 4050,1680 4100,1680 4150,1680 4200,1680 4250,1680 4300,1680 4350,1680 4400,1680 4450,1680 4500,1680 3800,1730 3850,1730 3900,1730 3950,1730 4000,1730 4050,1730 4150,1730 4200,1730 4250,1730 4300,1730 4400,1730 4450,1730 4500,1730 3800,1780 3850,1780 3900,1780 3950,1780 4000,1780 4050,1780 4100,1780 4150,1780 4200,1780 4250,1780 4300,1780 4350,1780 4400,1780 4450,1780 4500,1780 3800,1830 3850,1830 3900,1830 3950,1830 4000,1830 4050,1830 4100,1830 4150,1830 4200,1830 4250,1830 4300,1830 4350,1830 4400,1830 4450,1830 4500,1830
  other v3: 4900,75 4940,75 4980,75 5020,75 5060,75 5100,75 5150,75 5190,75 5230,75 5270,75 5310,75 5350,75 4900,115 4940,115 4980,115 5020,115 5060,115 5100,115 5150,115 5190,115 5230,115 5270,115 5310,115 5350,115 4900,155 4940,155 4980,155 5020,155 5060,155 5100,155 5150,155 5190,155 5230,155 5270,155 5310,155 5350,155 4900,195 4940,195 4980,195 5020,195 5060,195 5100,195 5150,195 5190,195 5230,195 5270,195 5310,195 5350,195 4900,681.27 5350,681.27 4900,721.27 5350,721.27 4900,761.27 4940,761.27 4980,761.27 5270,761.27 5310,761.27 5350,761.27
  other v9: 4100,1030 4350,1030 4100,1330 4350,1330 4100,1730 4350,1730
VBAT: C98.1 R52.1 R129.1 | length 2023.1
  Top Layer w12: R52.1@1986.5,5820 C98.1@2055,5820 ; C98.1@2050,5817.44 v7@2117.56,5817.44 ; v7(3595,5540) 3701.5,5540 R129.1@3810,5648.5 R129.1@3810,5653.5
  Signal Layer 5 w12: v7@2120,5815 2350,5585 2940,5585 2980,5625 3135,5625 3175,5585 3550,5585 v7(3595,5540)
  other v7: 2115,5820
VCC: C10.1 C34.1 C36.1 C96.1 C106.1 C107.1 C193.1 D1.2 D2.2 D4.2 D10.2 J4.2 L4.1 R12.2 R14.2 R157.2 R159.2 U1.19 U3.1 U4.1 U6.19 U8.7 U13.7 | length 16250.6
  Top Layer w12: C96.1@1850,5820 1850,5865 v9(1865,5880) ; C96.1@1851.5,5820 1851.5,5793.5 1875,5770 U8.7@1875,5728.35 U8.7@1875,5725 ; v4(2570,5835) 2605,5800 C107.1@2605,5740 2605,5666.5 C106.1@2611.5,5660 ; C106.1@2610,5660 2610,5630 2630,5610 U13.7@2630,5577.28 ; U3.1@5777.24,6422.6 5777.24,6387.76 5800,6365 C34.1@5910,6365
  Top Layer w16: R14.2@2670.47,3835 2670.47,3724.53 2675,3720 2915,3720 2941.54,3693.46 2941.54,3665 2941.54,3508.46 v4(3050,3400) 3854.42,3400 4429.42,3975 4430,3975 ; R12.2@3195,4505 3242.87,4457.13 3317.87,4457.13 3657.56,4117.44 R157.2@4185,4117.44 4292.56,4117.44 v4(4320,4090) 4570,3840 R159.2@4670.47,3840 4665,3834.53 4665,3720 4915,3720 4940,3695 v2(4940,3665) 4940,3425 4965,3400 v4(5050,3400) ; J4.2@5650,5140 J4.2@5650,5150 v11(5650,5695) 5910,5955 C36.1@5910,6185 ; U4.1@5785,6185 C36.1@5910,6185 ; C34.1@5915,6370 5975,6370 5990,6355 5990,6205 5970,6185 C36.1@5910,6185
  Signal Layer 1 w12: v4(2570,5835) 2735,5835 2835,5735 3125,5735 3290,5900 3630,5900 3655,5925 3785,5925 3810,5900 5445,5900 v11(5650,5695)
  Signal Layer 2 w16: v4@4525,4290 v4(4530,4295) 4595,4360 5055,4360 5073.13,4378.13 5478.13,4378.13 ; v4(5540,4380) 5490,4380 ; 5478.13,4378.13 5488.13,4378.13 5490,4380 ; 5478.13,4378.13 5480,4380 5490,4380
  Signal Layer 3 w12: v4(2570,5835) 2570,6745 v4(2630,6805) ; J4.2@5650,5135 J4.2@5655,5140
  Signal Layer 3 w16: v4(4320,4090) 4525,4295 v4(4530,4295) ; v4(5540,4380) 5540,4860 5650,4970 J4.2@5650,5135
  Signal Layer 5 w12: v9(1865,5880) 2150,5880 2195,5835 v4(2570,5835)
  Bottom Layer w9.8: 3070,3600 3090.16,3619.32 U1.19@3090.16,3681.54 ; 5090.16,3620.16 U6.19@5090.16,3677.6
  Bottom Layer w12: v4(2630,6805) 2630,6645 2795,6480 3175,6480 3345,6650 L4.1@3345,6758.5 ; 5055,3585 5090.16,3620.16
  Bottom Layer w16: C10.1@3050,3510 C10.1@3060,3520 ; 3060,3590 3070,3600
  Bottom Layer w19: C10.1@3060,3520 3060,3589.17
  Bottom Layer w20: D4.2@5010,3395 5015,3400 v4(5050,3400) D10.2@5130,3400
  Bottom Layer w24: D1.2@3005.12,3400 v4(3050,3400) D2.2@3100,3400
  Bottom Layer w25: C193.1@5050,3500 5055,3505 5055,3585
  Bottom Layer w30: v4(5050,3400) 5050,3500 C193.1@5050,3510
  Bottom Layer w32: v4(3050,3400) C10.1@3050,3510
  other v4: 2941.54,3685
VCCA: C11.1 C194.1 R14.1 R159.1 U1.31 U6.31 | length 2802.7
  Top Layer w12: R14.1@2728.35,3839.53 2789.53,3839.53 2805,3855 v4(2845,3855) 2855,3845 C11.1@2902.44,3845 ; R159.1@4725,3840 R159.1@4729.53,3840 4785,3840 4800,3855 v4(4845,3855) 4855,3845 C194.1@4902.44,3845 C194.1@4905,3845
  Signal Layer 5 w15: v4(2845,3855) 3017.37,4027.37 3697.37,4027.37 3725,4055 4070,4055 4235,3890 4235,3850 ; 4240,3845 4235,3850 ; v4(4845,3855) 4775,3855 4732.37,3812.37 4271.25,3812.37 4233.63,3850 4235,3850
  Bottom Layer w9.8: v4(2845,3855) 2850.16,3849.84 U1.31@2941.54,3849.84
  Bottom Layer w11: v4@4850.16,3849.84 U6.31@4937.6,3849.84
  Bottom Layer w12: v4(4845,3855) v4@4850.16,3849.84
VINX: R1.1 R5.1 R8.1 R43.1 U1.4 U6.4 | length 3306.3
  Signal Layer 2 w9: v4(2745,3785) 2780,3820 2870,3820 3015,3965 3265,3965 v4(3340,3890) ; v4(4745,3785) 4780,3820 4870,3820 5015,3965 5265,3965 v4(5340,3890)
  Signal Layer 5 w12: v4@3340.87,3889.13 v4(3340,3890) 3425,3975 4070,3975 4220,3825 4260,3785 v4(4745,3785)
  Bottom Layer w8: U1.4@3258.46,3889.21 3319.21,3889.21 ; 3320,3890 v4(3340,3890) 3365,3915 R5.1@3382.44,3915 ; U6.4@5262.4,3889.21 5339.21,3889.21 v4(5340,3890) 5360,3890 R43.1@5385,3915
  Bottom Layer w9: R1.1@2717.44,3750 2717.44,3777.44 2725,3785 v4(2745,3785)
  Bottom Layer w12: R8.1@4720,3750 4720,3785 v4(4745,3785)
Vocm1: C131.1 U19.2 | length 95.9
  Top Layer w12: U19.2@3980,6440 4020,6440 4050,6410 C131.1@4063.5,6410
Vocm2: C132.1 U20.2 | length 94.9
  Top Layer w9.8: U20.2@3987.6,5822.2 4012.8,5822.2 4055,5780 C132.1@4063.5,5780 C132.1@4065,5780
VREF: J18.6 J18.8 R84.2 | length 1578.7
  Top Layer w10: v4@1665,6390 v4(1660,6390) 1685,6365 1685,6275 1715,6245 R84.2@1738.5,6245 ; R84.2@1740,6245 R84.2@1740,6250
  Signal Layer 5 w10: v4(1660,6390) 1660,6520 1945,6805 2555,6805 J18.6@2650,6900
  Bottom Layer w10: J18.6@2650,6900 J18.8@2750,6900
pads on no net: FID1.1 FID2.1 FID3.1 FID4.1 FID5.1 FID6.1 H1.1 H2.1 H3.1 H4.1 H5.0 H6.0 H7.0 H8.0 H9.1 H10.1 H11.0 H12.0 J17.1 J17.10 J20.6 J20.7 J20.8 J20.9 J20.10 J20.11 L1.MP L2.MP L5.MP L6.MP LBL1.0 Q16.3 S3.4 S3.5 S3.6 U1.3 U1.5 U1.7 U1.16 U1.21 U1.32 U2.1 U2.2 U2.3 U3.4 U4.4 U5.11 U6.3 U6.5 U6.7 U6.16 U6.21 U6.32 U8.1 U8.5 U8.8 U9.12 U9.13 U9.14 U10.1 U14.1 U14.5 U14.8 U15.1 U15.5 U15.8 U16.1 U16.3 U16.7 U16.8 U17.5 U17.11 U21.24 U22.1 U22.3 U22.7 U22.8 U23.1 U23.2 U23.3 U23.4 U23.5 U23.6 U23.11 U23.12 U23.13 U23.14 U23.15 U23.19 U23.20 U23.21 U23.22 U23.23 U23.24 U23.25 U23.27 U23.31 U23.32 U23.40 U23.41 U23.42 U23.43 U23.44 U23.45 U23.46 U23.49 U23.50 U23.53 U23.54 U23.56 U23.57 U23.60 U23.61 U23.62 U23.63 U23.65 U23.71 U23.72 U23.73 U23.74 U23.75 U23.76 U23.77 U23.78 U23.93 U23.94 U23.95 U23.96 U23.102 U23.107 U23.108 U23.109 U23.110 U23.116 U23.117 U23.118 U23.119 U23.120 U23.121 U23.123 U23.124 U23.125 U23.126 U23.127 U23.128 U24.5 U24.7@4457.28,6730 U24.7@4492.72,6730 U26.5 U27.12 U27.15 U27.16 U27.17
copper on no net: | length 2131.9
  Top Layer w10: v4@2505,4460 v4(2500,4460) 2500,4515 2707.13,4722.13 2791.85,4722.13 3029.72,4960 3425,4960 3510,5045 v4(3510,5090) ; 3385,5350 3390,5355 ; 3390,5358.5 3390,5355 ; 3395,5280 3390,5285 3390,5355 ; v4(3440,5355) 3390,5355 ; 3456.5,5280 v4(3510,5280) v4@3515,5280
  Signal Layer 3 w10: 2090,5809.57 2090.13,5809.7 2090.13,5830.3 2090,5830.43 ; v4(3510,5090) v4(3510,5280)
  Signal Layer 6 w10: 2452.4,2287.87 2455.28,2285
  Bottom Layer w10: 3060,5370 3425,5370 v4(3440,5355)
